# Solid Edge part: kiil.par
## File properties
Author: Cymax
Template: Normal.par
Last saved by: Cymax
Revision: 7
Application: Solid Edge
Accuracy: 0,990
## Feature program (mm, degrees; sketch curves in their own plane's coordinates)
lofted protrusion "unnamed LoftedProtrusion 1"
fillet "unnamed Round 1"
sketch for "ExtrudedProtrusion_2" #1 plane through (-468.2059, 0.3224, 0) normal (0, 0, 1) x-axis (0, 1, 0)
sketch for "ExtrudedProtrusion_2" #2 plane through (-468.2059, 0.3224, 0) normal (0, 0, 1) x-axis (0, 1, 0)
  circle centre (-0.3224, -83.7384) radius 75
extrude "ExtrudedProtrusion_2" add finite 90 along +normal
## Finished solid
Body 1: solid body, 10 faces, 15 edges, 7 vertices.
  Faces by surface: plane 4, blend 2, cylinder 2, spline 2
  Edges by curve: intersection 7, circle 6, line 1, spline 1
Bounding box of the edges (mm; curved faces can reach further): 2241.512 x 533.083 x 1390.743, from (-1584.4676, -266.5335, -1300.7431) to (657.0446, 266.55, 90).
Cylindrical faces by radius (mm): R75 x2
Planar faces by outward normal: +z 3, oblique 1
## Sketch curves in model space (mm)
circle centre (-1284.4676, 0, 0) radius 75
circle centre (-384.4676, 0, 0) radius 75
line (-1199.374, 0, -1400) -> (-1199.374, -20.7435, -1400)
line (-1199.374, -20.7435, -1400) -> (-446.2247, -20.7435, -1400)
line (-446.2247, -20.7435, -1400) -> (-446.2247, 0, -1400)
line (-446.2247, 0, -1400) -> (-1199.374, 0, -1400)
arc centre (-1584.4676, 9250.471, 0) radius 9518.1716 from (-1584.4676, -267.7006, 0) through (-455.747, -200.5385, 0) to (657.0446, 0, 0)
line (-1584.4676, 267.7006, 0) -> (-1584.4676, -267.7006, 0)
arc centre (-1584.4676, -9250.471, 0) radius 9518.1716 from (-1584.4676, 267.7006, 0) through (-455.747, 200.5385, 0) to (657.0446, 0, 0)
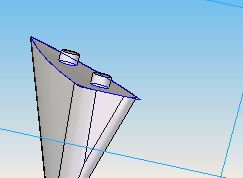
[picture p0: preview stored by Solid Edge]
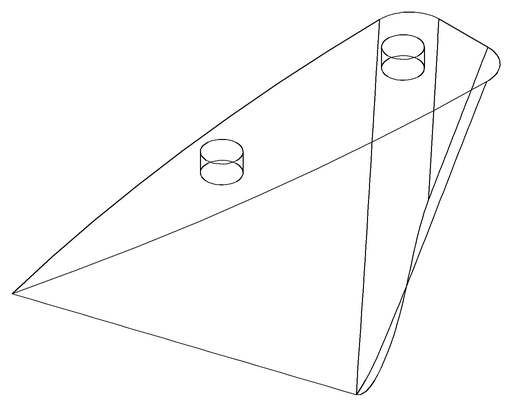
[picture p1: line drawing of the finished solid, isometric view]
